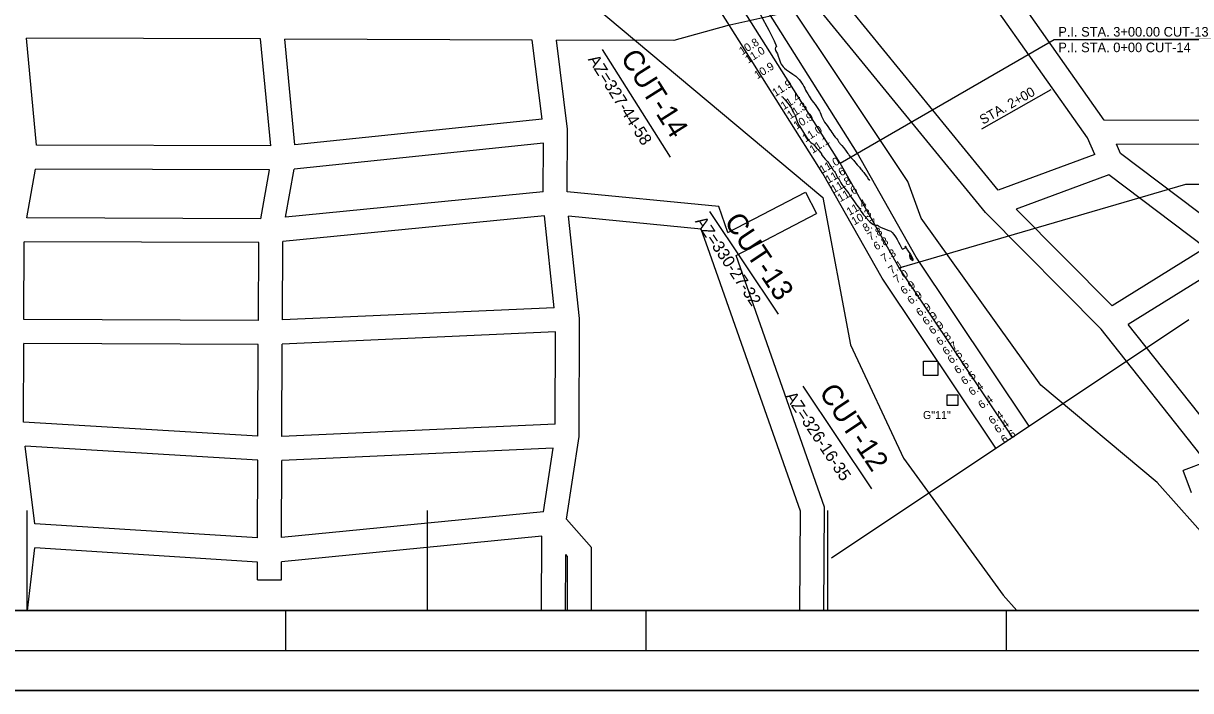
# Model space of a CAD drawing. Extents: x 497696 to 505896, y 1319278 to 1325078.
# Drawn here: x 500990 to 503906, y 1319278 to 1320945 of the extents above; entities that cross this region are included whole.
import ezdxf

# ---------------------------------------------------------------- set-up
doc = ezdxf.new("R2010")
doc.units = 0
for name, color, linetype in [('G-ANNO-TTLB', 7, 'Continuous'), ('Level 1', 7, 'Continuous'), ('Level 2', 7, 'Continuous'), ('Level 32', 7, 'Continuous'), ('Level 49', 7, 'Continuous'), ('Level 5', 7, 'Continuous'), ('Level 50', 7, 'Continuous'), ('Level 51', 7, 'Continuous'), ('Level 52', 7, 'Continuous'), ('Level 56', 7, 'Continuous'), ('Level 58', 7, 'Continuous'), ('Level 6', 7, 'Continuous')]:
    doc.layers.add(name, color=color, linetype=linetype)

msp = doc.modelspace()

# ---------------------------------------------------------------- linework, layer by layer
at = {"layer": 'G-ANNO-TTLB'}
for p, q in [((505696.2, 1319477.9), (498046.2, 1319477.9)), ((501646.2, 1319377.9), (501646.2, 1319477.9)), ((502546.2, 1319377.9), (502546.2, 1319477.9)), ((503446.2, 1319377.9), (503446.2, 1319477.9)), ((497796.2, 1319377.9), (505796.2, 1319377.9))]:
    msp.add_line(p, q, dxfattribs=at)
for points in [[(497696.2, 1319277.9), (505896.2, 1319277.9), (505896.2, 1325077.9), (497696.2, 1325077.9)], [(497696.2, 1319277.9), (505896.2, 1319277.9), (505896.2, 1325077.9), (497696.2, 1325077.9)], [(497696.2, 1325077.9), (505896.2, 1325077.9), (505896.2, 1319277.9), (497696.2, 1319277.9)]]:
    msp.add_lwpolyline(points, close=True, dxfattribs=at)
at = {"layer": 'Level 1'}
for p, q in [((501646.2, 1319377.9), (501646.2, 1319477.9)), ((502546.2, 1319377.9), (502546.2, 1319477.9)), ((503446.2, 1319377.9), (503446.2, 1319477.9))]:
    msp.add_line(p, q, dxfattribs=at)
for points in [[(497796.2, 1319377.9), (505796.2, 1319377.9), (505796.2, 1324977.9), (497796.2, 1324977.9)], [(498046.2, 1319477.9), (505696.2, 1319477.9), (505696.2, 1324877.9), (498046.2, 1324877.9)], [(503207.2, 1320356.4), (503212.7, 1320352.9), (503213.1, 1320354), (503211.3, 1320357.9), (503207.2, 1320364.8), (503204.6, 1320367.9), (503203.7, 1320367.5), (503204.4, 1320363.3), (503204.8, 1320360.6), (503205, 1320359.2), (503205, 1320359.1), (503205.2, 1320358.8), (503205.7, 1320358.2)]]:
    msp.add_lwpolyline(points, close=True, dxfattribs=at)
for points in [[(502832.1, 1320966.6), (502852.9, 1320928.3), (502866, 1320901.9), (502871.4, 1320887.4), (502869.2, 1320884.8), (502868.5, 1320881.6), (502869.3, 1320877.9), (502871.6, 1320873.7), (502873.9, 1320868.8), (502876.1, 1320863.1), (502878.4, 1320856.8), (502880.3, 1320851.4), (502882.1, 1320846.9), (502883.6, 1320843.2), (502885.7, 1320839.8), (502888.5, 1320836.6), (502891.9, 1320833.6), (502897.1, 1320829.5), (502904, 1320824.4), (502912.7, 1320818.3), (502919.6, 1320813), (502924.8, 1320808.5), (502928.2, 1320804.9), (502931.4, 1320800.9), (502934.5, 1320796.8), (502937.3, 1320792.4), (502940, 1320787.9), (502942.3, 1320783.4), (502944.5, 1320778.8), (502947, 1320774), (502950, 1320768.9), (502953.3, 1320763.7), (502956.2, 1320759.2), (502958.7, 1320755.3), (502960.7, 1320752.1), (502963.8, 1320747.8), (502967.9, 1320742.2), (502973, 1320735.5), (502976.9, 1320729.9), (502979.5, 1320725.6), (502980.7, 1320722.4), (502982.3, 1320718.5), (502984.2, 1320713.8), (502986.4, 1320708.4), (502989, 1320703.3), (502991.9, 1320698.5), (502995.1, 1320694.1), (502998.3, 1320689.7), (503001.3, 1320685.3), (503004.3, 1320680.8), (503007.1, 1320676.6), (503009.7, 1320672.8), (503012.2, 1320669.2), (503015.1, 1320665.4), (503018.5, 1320661.2), (503022.3, 1320656.7)], [(502884.4, 1320762.9), (502886.4, 1320761.5), (502887.3, 1320760.8), (502888.1, 1320760.1), (502888.7, 1320759.4), (502891, 1320756.7), (502894.8, 1320752.1), (502900.3, 1320745.6), (502905, 1320739.3), (502908.8, 1320733.1), (502911.7, 1320727.1), (502914.1, 1320722.6), (502915.8, 1320719.6), (502916.9, 1320718.1), (502918.4, 1320714.8), (502920.3, 1320709.7), (502922.5, 1320702.8), (502925.2, 1320696.2), (502928.4, 1320689.9), (502932.1, 1320683.8), (502936.5, 1320676.7), (502941.7, 1320668.6), (502947.7, 1320659.4), (502952.9, 1320652.5), (502957.3, 1320647.8), (502961, 1320645.4), (502963.8, 1320643.2), (502965.6, 1320641.3), (502966.5, 1320639.8), (502968.9, 1320636.9), (502972.8, 1320632.7), (502978.2, 1320627.2), (502981.9, 1320622.9), (502984, 1320619.7), (502984.4, 1320617.7), (502986.1, 1320614.8), (502989.1, 1320611), (502993.4, 1320606.2), (502997, 1320602.3), (502999.7, 1320599.3), (503001.8, 1320597.2), (503003.4, 1320595.1), (503004.5, 1320593.1), (503005.3, 1320591.1), (503007, 1320588.1), (503009.8, 1320584), (503013.5, 1320578.9), (503016.4, 1320575.1), (503018.3, 1320572.6), (503019.4, 1320571.4), (503020.3, 1320569.8), (503020.9, 1320567.8), (503021.2, 1320565.5), (503022.1, 1320563.2), (503023.6, 1320560.8), (503025.7, 1320558.4), (503027.9, 1320555.4), (503030.2, 1320551.6), (503032.5, 1320547.1), (503034.9, 1320543), (503037.3, 1320539.3), (503039.7, 1320536), (503042.4, 1320532.5), (503045.4, 1320528.6), (503048.8, 1320524.4)], [(503022.3, 1320656.7), (503025.1, 1320653.1), (503027, 1320650.4), (503027.8, 1320648.5), (503028.9, 1320646.7), (503030.3, 1320645), (503031.9, 1320643.3), (503034.7, 1320640), (503038.7, 1320635.1), (503043.8, 1320628.6), (503047.7, 1320623.7), (503050.1, 1320620.2), (503051.3, 1320618.2), (503053.5, 1320615.2), (503057, 1320611.1), (503061.6, 1320606), (503064.8, 1320602.3), (503066.7, 1320600), (503067.3, 1320599), (503069.5, 1320596.3), (503073.3, 1320591.9), (503078.7, 1320585.7), (503082.5, 1320581.4), (503084.6, 1320578.9), (503085.2, 1320578.2), (503086.9, 1320576), (503089.6, 1320572.4), (503093.5, 1320567.4), (503096.5, 1320563.2), (503098.7, 1320559.9), (503100.1, 1320557.5), (503101.1, 1320556), (503101.6, 1320555.5), (503101.7, 1320556), (503102, 1320555.9), (503102.6, 1320555.3), (503104.3, 1320552.9)], [(503048.8, 1320524.4), (503052.1, 1320520.1), (503055.3, 1320515.6), (503058.6, 1320510.9), (503062.5, 1320505.4), (503066.9, 1320499.2), (503071.9, 1320492.2), (503076.2, 1320486.1), (503079.6, 1320480.7), (503082.3, 1320476.1), (503085.4, 1320471.6), (503089, 1320467.3), (503093, 1320463), (503096.1, 1320459.6), (503098.1, 1320457), (503099.2, 1320455.2), (503101.5, 1320452.6), (503104.9, 1320449.3), (503109.6, 1320445.2), (503113.8, 1320442.5), (503117.8, 1320441.2), (503121.4, 1320441.3), (503124.4, 1320440.8), (503126.7, 1320439.7), (503128.3, 1320438), (503131.8, 1320436), (503137.1, 1320433.5), (503144.3, 1320430.7), (503150.1, 1320428.5), (503154.5, 1320426.8), (503157.6, 1320425.7), (503161.1, 1320422.8), (503165, 1320418), (503169.3, 1320411.5), (503173.3, 1320405.2), (503176.8, 1320399), (503179.9, 1320392.9), (503182.2, 1320388.1), (503183.7, 1320384.6), (503184.5, 1320382.4), (503186.1, 1320381.4), (503188.5, 1320381.7), (503191.7, 1320383.2), (503193.6, 1320384.8), (503194.1, 1320386.6), (503193.3, 1320388.4), (503195.1, 1320385.9), (503199.3, 1320378.9), (503206.1, 1320367.4), (503210.6, 1320359.9), (503212.7, 1320356.3), (503212.4, 1320357.1)]]:
    msp.add_lwpolyline(points, dxfattribs=at)
at = {"layer": 'Level 2'}
for p, q in [((501000, 1319477.9), (501000, 1319727.9)), ((502000, 1319477.9), (502000, 1319727.9)), ((503000, 1319477.9), (503000, 1319727.9))]:
    msp.add_line(p, q, dxfattribs=at)
at = {"layer": 'Level 32'}
for p, q in [((503648.9, 1320658.9), (503403.7, 1321006.9)), ((503690.7, 1320703.7), (503476.3, 1321008)), ((503425.8, 1320528.5), (503057.9, 1320978.3)), ((502904.9, 1320973.9), (502747.4, 1320939.1)), ((503393.9, 1320472.8), (502984.3, 1320973.6)), ((502747.4, 1320939.1), (502614.9, 1320902.3)), ((501022.9, 1320641.3), (500997.6, 1320908.6)), ((501582.9, 1320906.3), (500997.6, 1320908.6)), ((501608.2, 1320639), (501582.9, 1320906.3)), ((501668.2, 1320641.9), (501643.2, 1320906.1)), ((502261.5, 1320903.7), (501643.2, 1320906.1)), ((502285.9, 1320705.7), (502261.5, 1320903.7)), ((502349.4, 1320680.7), (502322, 1320903.4)), ((502614.9, 1320902.3), (502322, 1320903.4)), ((502285.9, 1320705.7), (501668.2, 1320641.9)), ((504062.1, 1320702.2), (503690.7, 1320703.7)), ((502348.8, 1320524.4), (502349.4, 1320680.7)), ((503666.9, 1320617.9), (503648.9, 1320658.9)), ((501608.2, 1320639), (501022.9, 1320641.3)), ((502289.2, 1320645.7), (501666.7, 1320581.4)), ((502288.8, 1320524.4), (502289.2, 1320645.7)), ((503731.5, 1320620.1), (503721.2, 1320643.5)), ((504093.8, 1320642.1), (503721.2, 1320643.5)), ((503666.9, 1320617.9), (503425.8, 1320528.5)), ((504006.9, 1320411.6), (503731.5, 1320620.1)), ((500998.5, 1320459.6), (501020.6, 1320581.3)), ((501605.3, 1320579), (501020.6, 1320581.3)), ((501583.2, 1320457.3), (501605.3, 1320579)), ((501644.8, 1320461), (501666.7, 1320581.4)), ((503702.2, 1320567), (503470.3, 1320481)), ((503943.9, 1320384.1), (503702.2, 1320567)), ((502288.8, 1320524.4), (501644.8, 1320461)), ((502727.9, 1320487.3), (502348.8, 1320524.4)), ((502750.5, 1320422.5), (502944.3, 1320523.2)), ((502944.3, 1320523.2), (502972, 1320469.9)), ((502750.5, 1320422.5), (502727.9, 1320487.3)), ((501583.2, 1320457.3), (500998.5, 1320459.6)), ((502292, 1320464.4), (501638.1, 1320400)), ((502316.6, 1320234.8), (502292, 1320464.4)), ((502683.9, 1320431.3), (502352.4, 1320463.7)), ((502379.8, 1320207.8), (502352.4, 1320463.7)), ((502770.6, 1320365.3), (502972, 1320469.9)), ((503683.1, 1320181), (503393.9, 1320472.8)), ((503710.1, 1320239.1), (503470.3, 1320481)), ((502705.3, 1320370.1), (502683.9, 1320431.3)), ((500991.7, 1320205.2), (500992.5, 1320399.7)), ((501578.1, 1320397.4), (500992.5, 1320399.7)), ((501577.3, 1320202.9), (501578.1, 1320397.4)), ((501637.3, 1320204.2), (501638.1, 1320400)), ((503943.9, 1320384.1), (503710.1, 1320239.1)), ((503989.6, 1320341.8), (503750, 1320193.2)), ((502316.6, 1320234.8), (501637.3, 1320204.2)), ((501577.3, 1320202.9), (500991.7, 1320205.2)), ((502378.7, 1319913.1), (502379.8, 1320207.8)), ((503996.1, 1319882.8), (503750, 1320193.2)), ((502319.7, 1320174.8), (501637.1, 1320144.1)), ((502318.8, 1319944.1), (502319.7, 1320174.8)), ((503945.5, 1319850.1), (503683.1, 1320181)), ((500990.7, 1319949), (500991.5, 1320145.2)), ((501577.1, 1320142.9), (500991.5, 1320145.2)), ((501576.2, 1319913.8), (501577.1, 1320142.9)), ((501636.2, 1319913.3), (501637.1, 1320144.1)), ((501576.2, 1319913.8), (500990.7, 1319949)), ((502318.8, 1319944.1), (501636.2, 1319913.3)), ((502347.3, 1319706.7), (502378.7, 1319913.1)), ((501018.6, 1319694.6), (500994.8, 1319888.7)), ((501576, 1319853.7), (500994.8, 1319888.7)), ((502313.5, 1319883.8), (501636, 1319853.2)), ((502289.4, 1319724.9), (502313.5, 1319883.8)), ((501575.2, 1319659.4), (501576, 1319853.7)), ((501635.2, 1319660.5), (501636, 1319853.2)), ((503945.5, 1319850.1), (503887.3, 1319828.4)), ((503908.2, 1319772.2), (503887.3, 1319828.4)), ((502289.4, 1319724.9), (501635.2, 1319660.5)), ((501575.2, 1319659.4), (501018.6, 1319694.6)), ((502285.4, 1319664.3), (501635, 1319600.2)), ((502284.7, 1319477.9), (502285.4, 1319664.3)), ((501000.4, 1319477.9), (501018.4, 1319634.5)), ((501575, 1319599.3), (501018.4, 1319634.5)), ((502344.7, 1319477.9), (502345.2, 1319618.3)), ((501574.8, 1319554.8), (501575, 1319599.3)), ((501634.8, 1319554.6), (501635, 1319600.2)), ((501574.8, 1319554.8), (501634.8, 1319554.6))]:
    msp.add_line(p, q, dxfattribs=at)
for points in [[(502930.3, 1319477.9), (502931.3, 1319726.2), (502705.4, 1320370)], [(502990.3, 1319477.9), (502991.3, 1319736.3), (502770.6, 1320365.3)], [(502409.2, 1319477.9), (502409.9, 1319635.7), (502347.3, 1319706.7)], [(502349.2, 1319477.9), (502349.8, 1319613.1), (502345.2, 1319618.3)]]:
    msp.add_lwpolyline(points, dxfattribs=at)
at = {"layer": 'Level 5'}
for points in [[(501677.2, 1324877.9), (501378.4, 1324614.6), (500725.8, 1323766.4), (500625.2, 1323558.4), (500565.9, 1323241.9), (500572.6, 1322708.4), (500738.3, 1322374.6), (500985.2, 1322032), (501020.7, 1321975.5), (501090.8, 1321884.7), (501394.4, 1321835.2), (501726.7, 1321794.1), (502293.5, 1321269.9), (502409.4, 1320994.5), (502987.7, 1320510.5), (503056.9, 1320142.4), (503189.4, 1319858.7), (503438.4, 1319516.2), (503472.5, 1319477.9)], [(504107.7, 1319477.9), (503822.6, 1319798.4), (503531.7, 1320041), (503232.9, 1320458.6), (503199.8, 1320550.4), (502737.7, 1321243.7), (502440.6, 1321661.5), (502255.8, 1321845.1), (502052.9, 1321934.2), (501254.5, 1322198), (501046.8, 1322407), (500972.3, 1322582.2), (500898.1, 1322849.2), (500933, 1323374.1), (501045.4, 1323950.4), (501078.5, 1324015.1), (501460.9, 1324322.7), (501588.1, 1324548.9), (501884.4, 1324877.9)]]:
    msp.add_lwpolyline(points, dxfattribs=at)
at = {"layer": 'Level 50'}
for p, q in [((503073.4, 1320621.5), (502644.3, 1321301.7)), ((502987.6, 1320570.1), (502563, 1321243.1)), ((503221, 1320361), (503073.4, 1320621.5)), ((503135.8, 1320308.5), (502987.6, 1320570.1)), ((503502.6, 1319939.2), (503221, 1320361)), ((503419.4, 1319883.6), (503135.8, 1320308.5))]:
    msp.add_line(p, q, dxfattribs=at)
at = {"layer": 'Level 51'}
for p, q in [((502607.3, 1320610.6), (502437.1, 1320880.4)), ((502876.4, 1320218.5), (502704.8, 1320475.5)), ((503110.1, 1319781.9), (502938.5, 1320038.9))]:
    msp.add_line(p, q, dxfattribs=at)
at = {"layer": 'Level 52'}
for points in [[(503238.7, 1320101.3), (503274.7, 1320101.3), (503274.7, 1320065.3), (503238.7, 1320065.3)], [(503298.5, 1319990.6), (503298.5, 1320016.7), (503324.7, 1320016.7), (503324.7, 1319990.6)]]:
    msp.add_lwpolyline(points, close=True, dxfattribs=at)
at = {"layer": 'Level 56'}
for p, q in [((503030.5, 1320595.8), (503565.8, 1320904.8)), ((503565.8, 1320904.8), (504029.7, 1320904.8)), ((504029.7, 1320904.8), (503684, 1320904.8)), ((503384.3, 1320681.4), (503558.3, 1320780)), ((503178.4, 1320334.8), (503894.6, 1320543.3)), ((503894.6, 1320543.3), (504358.6, 1320543.3))]:
    msp.add_line(p, q, dxfattribs=at)
at = {"layer": 'Level 58'}
msp.add_line((503009.5, 1319610), (503901.9, 1320205.7), dxfattribs=at)
at = {"layer": 'Level 6'}
for p, q in [((503030.5, 1320595.8), (502603.6, 1321272.4)), ((503178.4, 1320334.8), (503030.5, 1320595.8)), ((503461, 1319911.4), (503178.4, 1320334.8))]:
    msp.add_line(p, q, dxfattribs=at)

# ---------------------------------------------------------------- texts
at = {"layer": 'Level 49'}
for s, rotation, p in [('10.8 ', 32.2506, (502785.9, 1320865.4)), ('11.0 ', 32.2506, (502800.9, 1320844.4)), ('10.9 ', 32.2506, (502823.9, 1320805.4)), ('11.9 ', 32.2506, (502868.9, 1320761.4)), ('11.4 ', 32.2506, (502889.9, 1320728.4)), ('11.3 ', 32.2506, (502905.9, 1320705.4)), ('10.9 ', 32.2506, (502921.9, 1320679.4)), ('11.0 ', 32.2506, (502943.9, 1320647.4)), ('11.1 ', 32.2506, (502961.9, 1320619.4)), ('11.0 ', 29.5411, (502985.8, 1320569.3)), ('11.6 ', 29.5411, (503000.8, 1320544.3)), ('11.8 ', 29.5411, (503014.8, 1320520.3)), ('11.6 ', 29.5411, (503030.8, 1320498.3)), ('11.4 ', 29.5411, (503053.8, 1320464.3)), ('10.3 ', 29.5411, (503065.8, 1320440.3)), ('8.7', 29.5411, (503093.9, 1320423.5)), ('7.8', 29.5411, (503105.9, 1320401.5)), ('6.8', 29.5411, (503120.9, 1320377.5)), ('7.3', 29.5411, (503139.9, 1320347.5)), ('7.1', 33.7236, (503159.5, 1320317.4)), ('7.0', 33.7236, (503172.2, 1320294.5)), ('6.9', 33.7236, (503189.8, 1320266.9)), ('6.9', 33.7236, (503206.8, 1320241.9)), ('6.9', 33.7236, (503228.8, 1320211.9)), ('6.9', 33.7236, (503244.8, 1320189.9)), ('6.9', 33.7236, (503260.8, 1320166.9)), ('6.8', 33.7236, (503278.9, 1320139)), ('6.7', 33.7236, (503294.9, 1320115)), ('6.6', 33.7236, (503307.4, 1320093.7)), ('6.5', 33.7236, (503323.9, 1320068)), ('6.5', 33.7236, (503340.9, 1320041)), ('6.4', 33.7236, (503359.9, 1320014)), ('6.4', 33.7236, (503383.9, 1319981)), ('6.4', 33.7236, (503409.9, 1319942)), ('6.4', 33.7236, (503423.9, 1319920)), ('6.6', 33.7236, (503440.4, 1319894.7))]:
    msp.add_text(s, height=20, rotation=rotation, dxfattribs=at).set_placement(p)
at = {"layer": 'Level 51'}
for s, height, rotation, p in [('AZ=327-44-58', 30, 302.2505, (502399.7, 1320855.4)), ('CUT-14', 52, 302.2505, (502480.5, 1320860.3)), ('AZ=330-27-32', 30, 303.7235, (502667.4, 1320450.6)), ('CUT-13', 52, 303.7235, (502739.5, 1320450.7)), ('AZ=326-16-35', 30, 303.7235, (502892.2, 1320013.1)), ('CUT-12', 52, 303.7235, (502976.4, 1320023.6))]:
    msp.add_text(s, height=height, rotation=rotation, dxfattribs=at).set_placement(p)
at = {"layer": 'Level 52'}
msp.add_text('G"11"', height=20, dxfattribs=at).set_placement((503237.6, 1319956.7))
at = {"layer": 'Level 56'}
for s, p in [('P.I. STA. 3+00.00 CUT-13', (503575.7, 1320912.3)), ('P.I. STA. 0+00 CUT-14', (503575.7, 1320873.3))]:
    msp.add_text(s, height=24, dxfattribs=at).set_placement(p)
msp.add_text('STA. 2+00', height=24, rotation=29.6365, dxfattribs=at).set_placement((503387.5, 1320691.7))

doc.saveas('drawing.dxf')
